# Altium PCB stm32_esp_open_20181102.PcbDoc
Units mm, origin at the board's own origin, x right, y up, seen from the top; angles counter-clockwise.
Board outline 48.1 x 88.05 mm, 2 copper layers (Top Layer, Bottom Layer); 96 components, 69 nets, 304 pads, 149 vias.
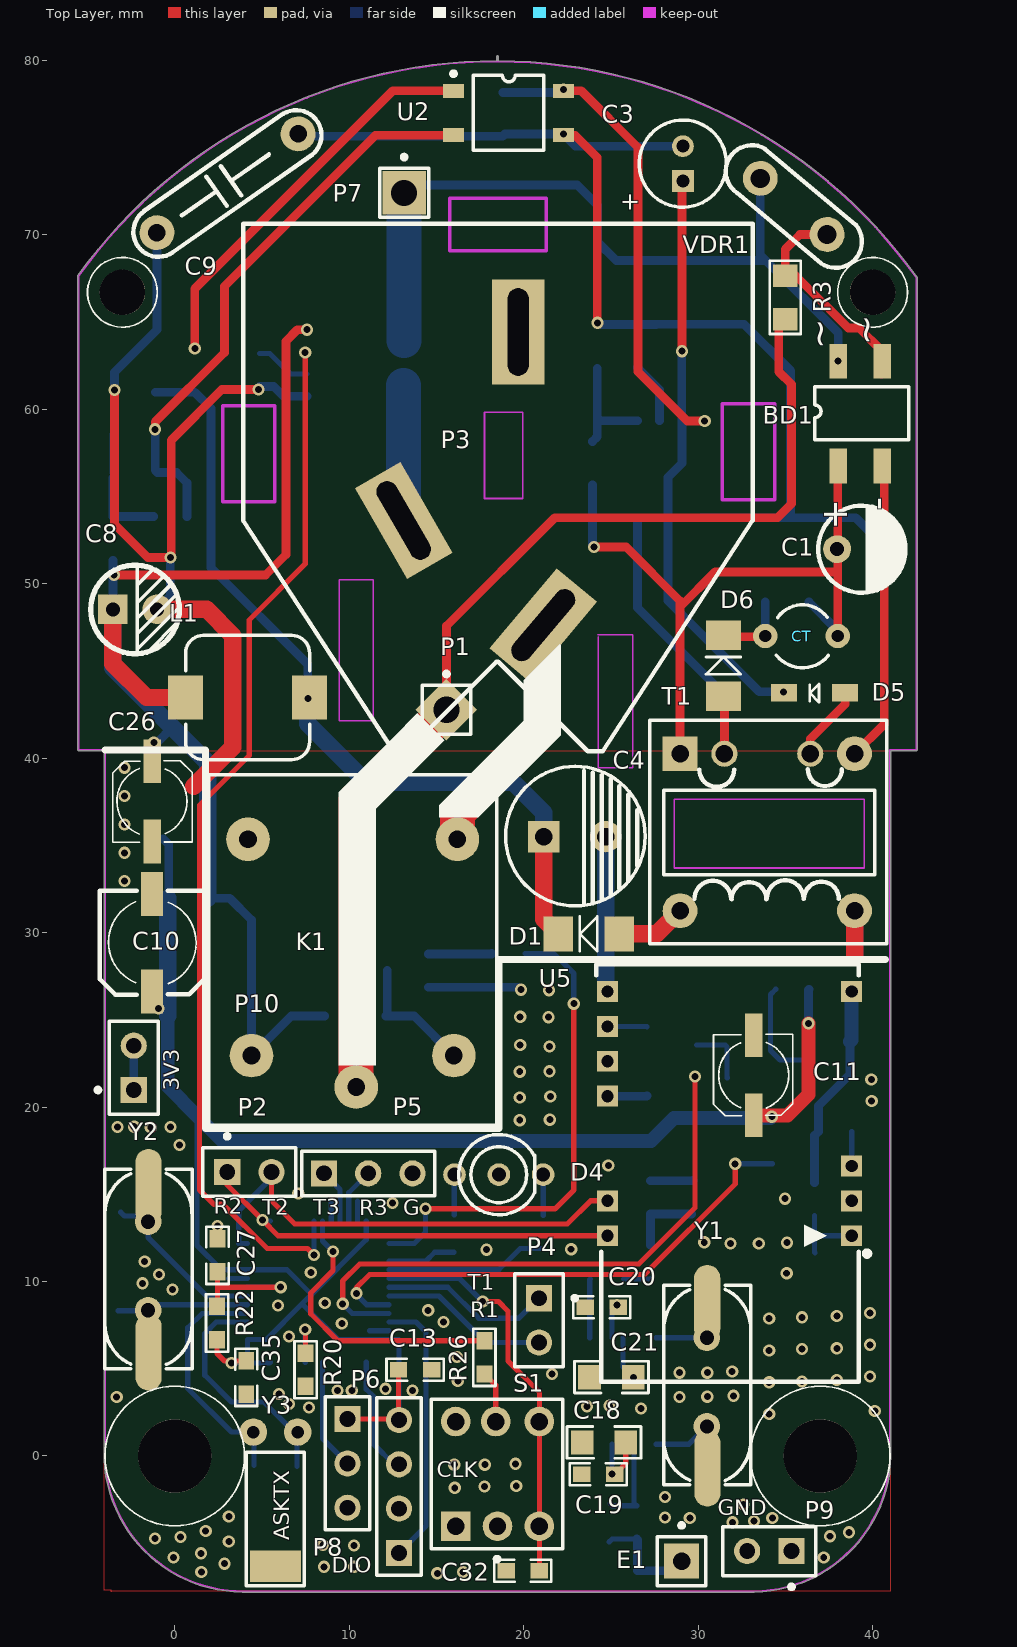
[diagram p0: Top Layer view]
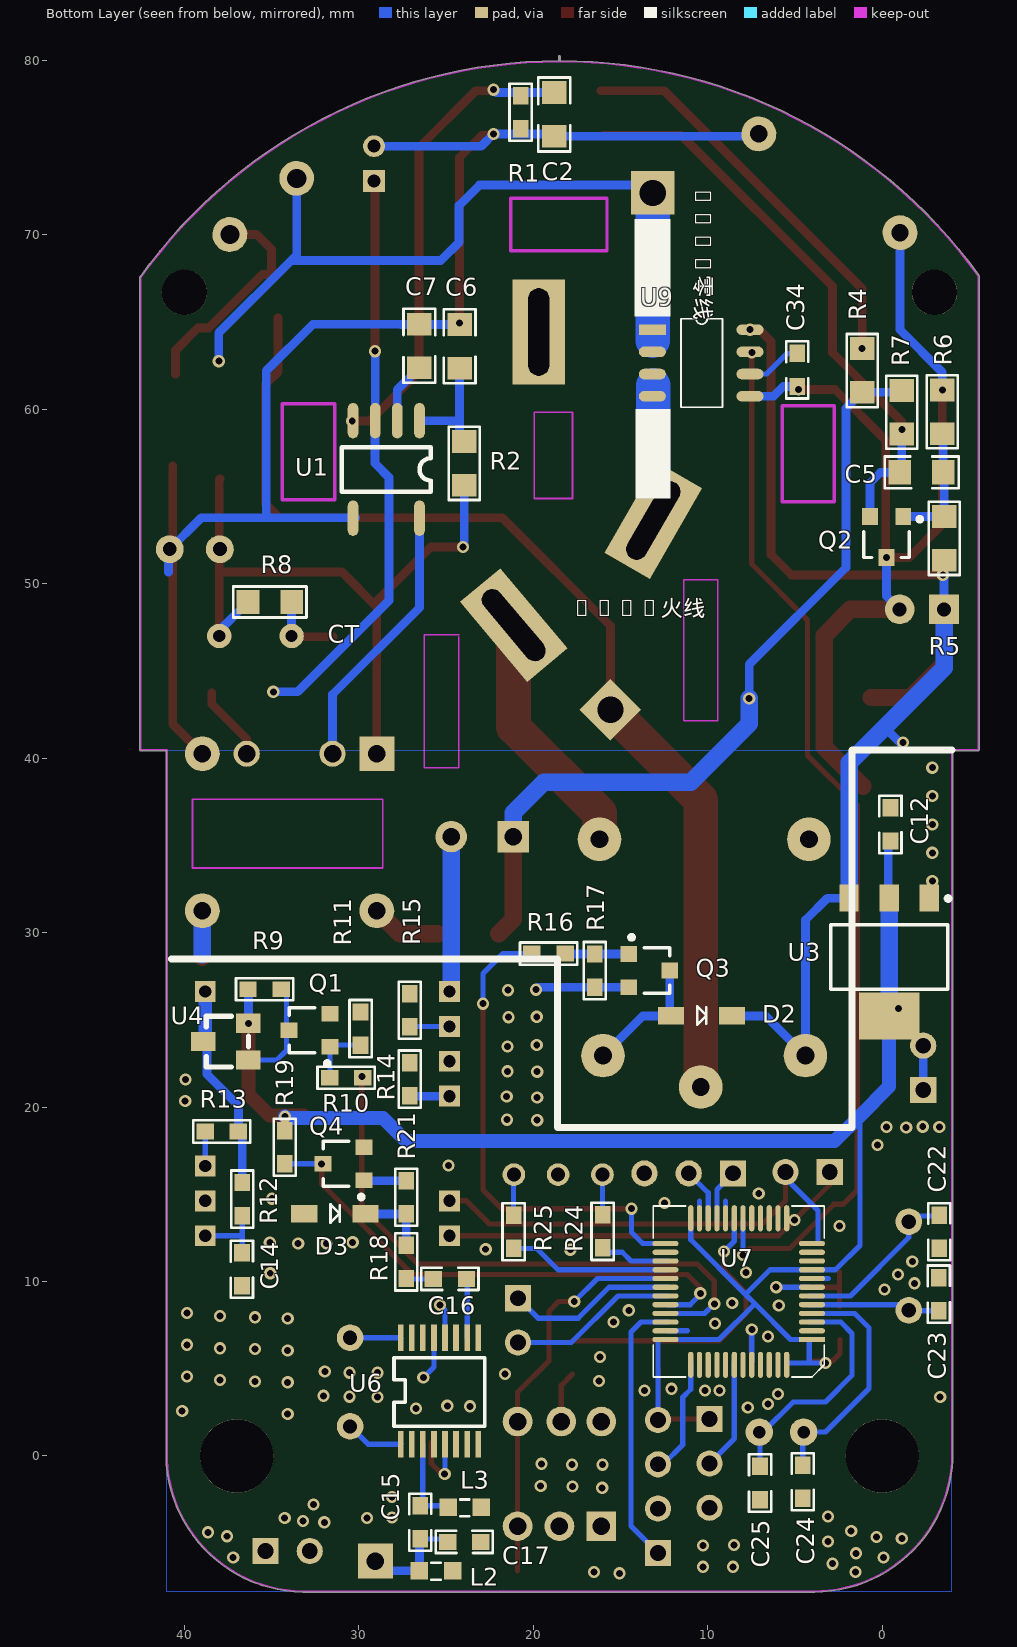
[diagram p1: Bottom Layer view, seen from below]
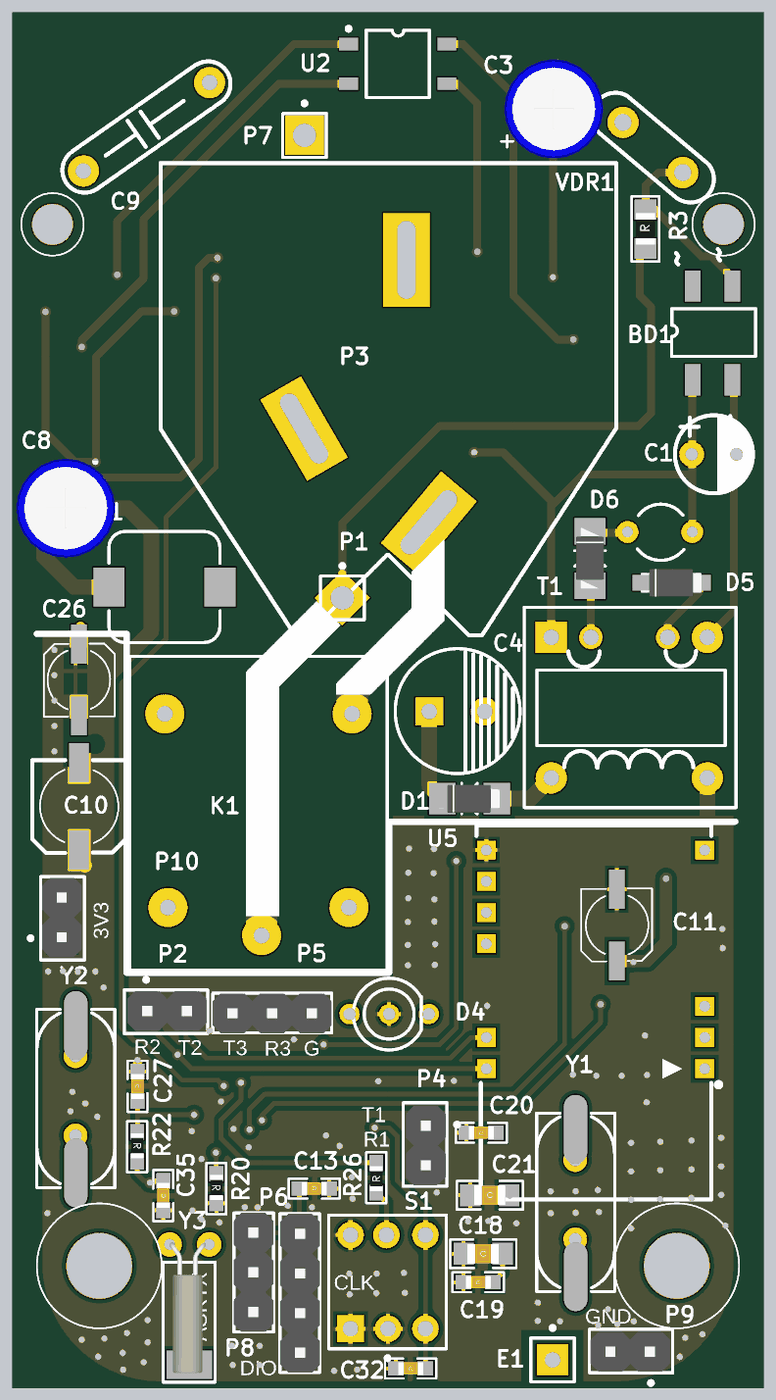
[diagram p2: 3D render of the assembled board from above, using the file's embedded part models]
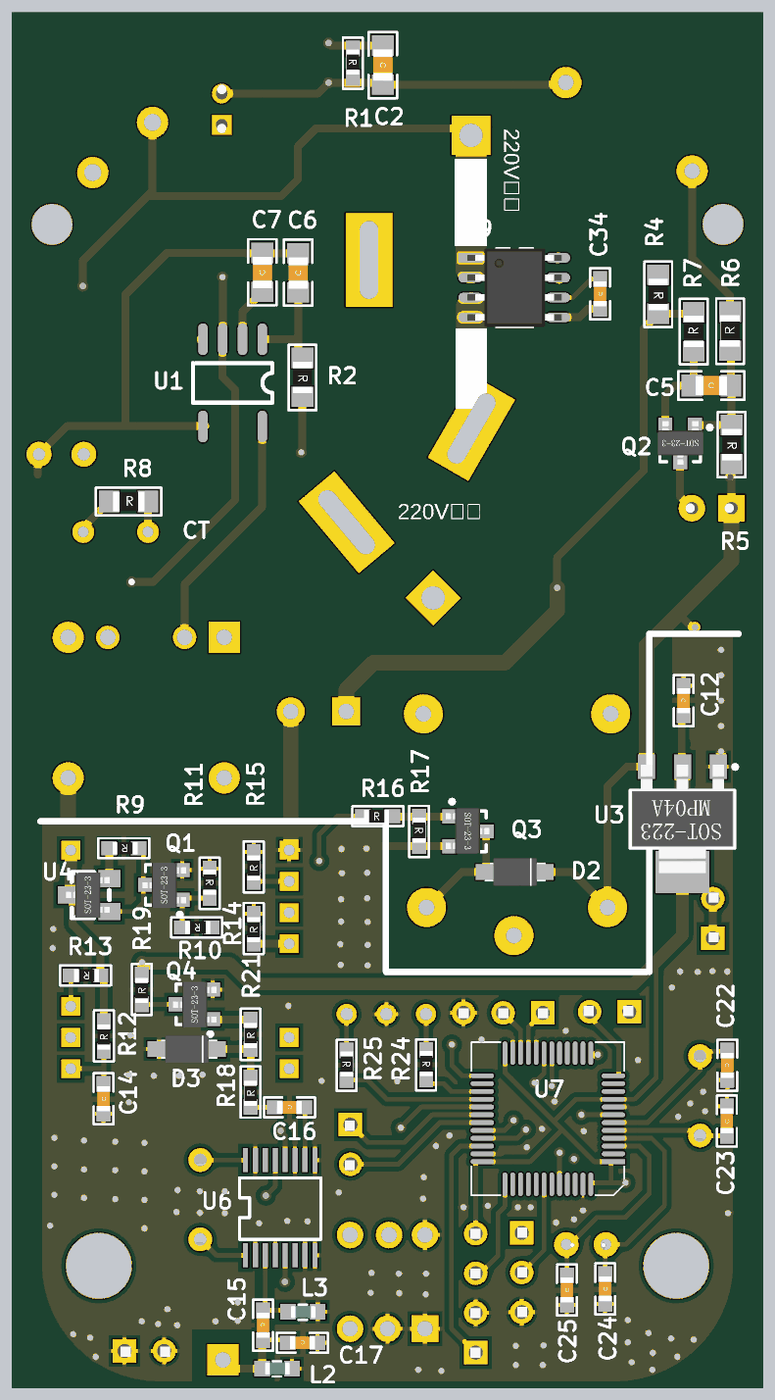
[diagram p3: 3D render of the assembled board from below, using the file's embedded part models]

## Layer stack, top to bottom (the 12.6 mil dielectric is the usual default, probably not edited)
Top Solder: solder mask 0.0102, Solder Resist, Dk 3.5
Top Layer: signal copper 0.0356
Dielectric 1: dielectric 0.32, FR-4, Dk 4.8
Bottom Layer: signal copper 0.0356
Bottom Solder: solder mask 0.0102, Solder Resist, Dk 3.5

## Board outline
-4.044,-0.198 cw(c-4,-0.172) -4.05,-0.172 -4.05,0.031 cw(c3.898,0.152) -4.051,0.049 cw(c-4,0.05) -4.05,0.055 -4.05,40.425 -5.5,40.425 cw(c-5.5,40.475) -5.55,40.475 -5.55,67.65 cw(c-5.5,67.65) -5.541,67.679 cw(c18.461,50.394) 18.45,79.972 18.45,80.2 cw(c18.5,80.2) 18.55,80.2 18.55,79.972 cw(c18.461,50.394) 42.529,67.588 cw(c42.5,67.546) 42.55,67.546 42.55,40.475 cw(c42.5,40.475) 42.5,40.425 41.05,40.425 41.05,0.025 cw(c41,0.025) 41.047,0.006 cw(c33.098,0.148) 33.201,-7.801 cw(c33.2,-7.75) 33.2,-7.801 3.898,-7.801 cw(c3.898,-7.75) 3.882,-7.798 cw(c3.898,0.152)

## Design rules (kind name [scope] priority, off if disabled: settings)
Clearance [All] p1: gap=0.3
PolygonConnect PolygonConnect_1 [isvia] p1: connectstyle=Direct reliefconductorwidth=0.254 reliefentries=4 polygonreliefangle="90 Angle" airgapwidth=0.254
PolygonConnect [All] p2: connectstyle=Relief reliefconductorwidth=0.254 reliefentries=4 polygonreliefangle="90 Angle" airgapwidth=0.254
RoutingVias [All] p1: holewidth=0.711 width=1.27 viastyle="Through Hole" minholewidth=0.711 minwidth=1.27 maxholewidth=0.711 maxwidth=1.27
SolderMaskExpansion [All] p1: expansion=0.102
Width [All] p1: maxlimit=10 minlimit=0.1 preferedwidth=0.254
30 further rules are at their usual default settings.

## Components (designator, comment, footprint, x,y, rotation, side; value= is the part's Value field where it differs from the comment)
BD1 "MB6S" MB6S 40.565,62.75 r270 top
C1 "4.7UF/400V" C-RB3_5X8mm 39.4,51.975 r0 top
C2 "0.01UF" CAP-0805 18.8,76.9 r270 bottom
C3 "22UF/50V" C-RB2_5x6.8mm 29.125,73.075 r90 top
C4 "1000UF/10V" C-RB3.5_8x12mm 22.925,35.503 r0 top
C5 "0.1UF" CAP-0805 -2.25,56.375 r180 bottom
C6 "0.01UF" CAP-0805 24.225,63.6 r90 bottom
C7 "331" CAP-0805 26.525,63.625 r90 bottom
C8 "220UF/10V" C-RB2.54_5x10mm -2.275,48.525 r0 top
C9 "Y-471M" C-RAD-Y_10mm 3.025,72.95 r215 top
C10 "220UF/6.3V" C-RB_S5mm -1.3,29.419 r90 top
C11 "220UF/6.3V" C-RB_S4mm 33.175,21.825 r90 top
C12 "0.1UF" CAP-0603 -0.475,36.2 r270 bottom
C13 "0.1UF" CAP-0603 13.775,4.95 r180 top
C14 "0.1UF" CAP-0603 36.7,10.7 r90 bottom
C15 "1.5PF" CAP-0603 26.475,-3.8 r270 bottom
C16 "0.1UF" CAP-0603 24.775,10.15 r0 bottom
C17 "5.6PF" CAP-0603 23.95,-4.925 r0 bottom
C18 "10UF" CAP-0805 24.6,0.775 r0 top
C19 "0.1UF" CAP-0603 24.275,-1.05 r0 top
C20 "0.1UF" CAP-0603 24.475,8.525 r0 top
C21 "10UF" CAP-0805 25.025,4.525 r0 top
C22 "20PF" CAP-0603 -3.275,12.85 r270 bottom
C23 "20PF" CAP-0603 -3.25,9.275 r90 bottom
C24 "20PF" CAP-0603 4.55,-1.475 r90 bottom
C25 "20PF" CAP-0603 7,-1.55 r90 bottom
C26 "220UF/6.3V" C-RB_S4mm -1.3,37.525 r270 top
C27 "0.1UF" CAP-0603 2.45,11.5 r270 top
C32 "0.1UF" CAP-0603 19.95,-6.575 r0 top
C34 "0.1UF" CAP-0603 4.875,62.25 r90 bottom
C35 "0.1UF" CAP-0603 4.1,4.5 r90 top
CT "222" C-RAD_4mm 35.925,47 r180 top
D1 "SR210" DIODE-1206 23.725,29.925 r180 top
D2 "1N4148" DIODE-1206_N 10.35,25.225 r180 bottom
D3 "1N4148" DIODE-1206_N 31.375,13.875 r180 bottom
D4 "LED2-DIP_1" LED-A3 18.575,16.125 r180 top
D5 "1N4148" DIODE-1206_N 36.675,43.75 r180 top
D6 "RS1M" DIODE-1206 31.45,45.3 r90 top
E1 "ANT_DIP" HDR1-ANT 29.05,-6.025 r0 top
K1 "10A继电器" SPDT-5 10.4,21.15 r90 top locked
L1 "10UH" IND-CD7_7X7mm 4.175,43.475 r180 top
L2 "24NH" IND-0603 24.625,-6.575 r0 bottom
L3 "39NH" IND-0603 22.975,-2.95 r0 bottom
P1 "220V_L" HDR1#1 15.575,42.775 r0 top
P2 "升级ESP" HDR2.54_2x1 4.275,16.275 r0 top
P3 "5孔插座" HDRFIVEHOLESOCHET 33.122,70.622 r180 top locked
P4 "COM_DEBUG" HDR2.54_2x1 20.875,7.775 r270 top
P5 "URAT3" HDR2.54_3X1 8.55,16.2 r0 top
P6 "SWD" HDR2.54_4X1 12.85,-5.555 r90 top
P7 "220V_N" HDR1#2 13.15,72.4 r0 top
P8 "RF" HDR2.54_3X1 9.9,2.115 r270 top
P9 "GND" HDR2.54_2x1 34.08,-5.45 r180 top
P10 "3V3" HDR2.54_2x1 -2.35,22.25 r90 top
Q1 "2N8050" SOT-23 32.825,24.4 r90 bottom
Q2 "T431" SOT-23 -0.25,52.675 r0 bottom
Q3 "2N8050" SOT-23 13.35,27.825 r270 bottom
Q4 "2N3904" SOT-23 30.875,16.75 r90 bottom
R1 "10K" RES-0603 20.725,77.975 r270 bottom
R2 "2.2M" RES-0805 23.95,58.15 r270 bottom
R3 "0R" RES-0805 35,65.15 r90 top
R4 "150R" RES-0805 1.15,63.475 r270 bottom
R5 "2.49K" RES-0805 -3.55,53.85 r270 bottom
R6 "2.4K" RES-0805 -3.45,58.6 r90 bottom
R7 "1K" RES-0805 -1.125,58.575 r90 bottom
R8 "100K" RES-0805 36.35,48.95 r180 bottom
R9 "100K" RES-0603 34.45,26.75 r0 bottom
R10 "10K" RES-0603 29.775,21.675 r0 bottom
R11 "47K" RES-0603 29.9,25.45 r270 bottom
R12 "10K" RES-0603 36.675,13.775 r90 bottom
R13 "100R" RES-0603 36.9,18.6 r0 bottom
R14 "0R" RES-0603 27.075,20.65 r90 bottom
R15 "1K" RES-0603 27.075,24.6 r90 bottom
R16 "4.7K" RES-0603 20.075,28.8 r180 bottom
R17 "47K" RES-0603 16.475,28.775 r270 bottom
R18 "1K" RES-0603 27.275,10.175 r90 bottom
R19 "1K" RES-0603 34.25,16.75 r90 bottom
R20 "100K" RES-0603 7.5,5.9 r270 top
R21 "10K" RES-0603 27.275,13.875 r90 bottom
R22 "100K" RES-0603 2.425,8.575 r270 top
R24 "1K" RES-0603 16.025,13.825 r270 bottom
R25 "510R" RES-0603 21.125,13.8 r270 bottom
R26 "1K" RES-0603 17.75,4.7 r90 top
S1 "带灯按钮" SW-PB6_B1 18.5,-1.025 r90 top locked
T1 "E10" EE10-6_10X9MM 28.965,40.25 r270 top
U1 "THX208" SOP-6 28.425,56.55 r270 bottom
U2 "356" SOP-4 19.125,76.98 r270 top
U3 "AMS1117" SOT-223 -0.4,28.6 r0 bottom
U4 "SI2301" SI2301 36.325,22.7 r180 bottom
U5 "ESP-12DIP" ESP_12DIP 38.8,12.625 r180 top locked
U6 "SYN500R" SO-16 27.6,0.679 r90 bottom
U7 "STM32F103C8T6" LQFP48 4.025,6.675 r0 bottom
U9 "ACS712" SOP-8 10.375,62.65 r180 bottom
VDR1 "7D471K" RES-DIP_5mm 35.475,71.625 r320 top
Y1 "13.560M" X-SM49T 30.525,4.3 r270 top
Y2 "8M" X-SM49T -1.5,10.95 r270 top
Y3 "32.768K" X-TC15-2DIP 7.045,1.371 r180 top

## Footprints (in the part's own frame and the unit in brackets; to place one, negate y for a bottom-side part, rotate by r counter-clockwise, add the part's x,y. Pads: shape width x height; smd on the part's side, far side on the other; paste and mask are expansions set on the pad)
C-RAD-Y_10mm [mm] "插件 2脚 10mm间距 开关电源高压Y电容"
  round 2 hole 1: 1(-4.938,0) 2(4.938,0)
  silkscreen extent -6.25,-1.44 6.27,1.45
C-RAD_4mm [mm] "插件 2脚 4mm间距"
  round 1.4 hole 0.7: 1(-2.074,0) 2(2.074,0)
  silkscreen extent -1.54,-1.78 1.44,1.82
C-RB2.54_5x10mm [mm] "插件 2脚 2.54mm间距"
  rect 1.7x1.7 hole 0.8: 1(-1.27,0)
  round 1.7 hole 0.8: 2(1.27,0)
  silkscreen extent -2.54,-2.54 2.54,2.54, body extent -3.05,-3.17 3.3,3.18, height 11.53
C-RB2_5x6.8mm [mm] "插件 2脚 2mm间距"
  rect 1.25x1.25 hole 0.75: 1(0,0)
  round 1.25 hole 0.75: 2(2,0)
  silkscreen extent -1.5,-2.5 3.5,2.5, body extent -2.16,-3.18 4.19,3.18, height 11.53
C-RB3.5_8x12mm [mm] "插件 2脚 3.5mm间距 直径8mm 高12mm"
  rect 1.8x1.8 hole 1: 1(-1.778,0)
  round 1.8 hole 1: 2(1.778,0)
  silkscreen extent -3.96,-3.97 4.04,4.03
C-RB3_5X8mm [mm] "插件 2脚 3mm间距"
  round 1.6 hole 0.8: 1(-1.435,0) 2(1.435,0)
  silkscreen extent -2.51,-2.5 2.49,2.5
C-RB_S4mm [mm] "贴片 直径4mm高 5.4mm"
  rect 2.5x1 smd: 1(-2.3,0) 2(2.3,0)
  silkscreen extent -2.32,-2.25 2.35,2.3
C-RB_S5mm [mm] "贴片 直径5mm 高5.4mm"
  rect 2.5x1.27 smd: 1(-2.794,0) 2(2.794,0)
  silkscreen extent -2.97,-3 2.97,3
CAP-0603 [mm] "贴片 长宽1.6x0.8mm"
  rect 1x0.9 smd: 1(-0.95,0) 2(0.95,0)
  silkscreen extent -1.64,-0.64 1.64,0.64, body extent -0.79,-0.41 0.81,0.4, height 0.88
CAP-0805 [mm] "贴片 长宽2.0x1.2mm"
  rect 1.3x1.4 smd: 1(-1.25,0) 2(1.25,0)
  silkscreen extent -2.11,-0.91 2.13,0.91, body extent -1.01,-0.62 1,0.63, height 0.92
DIODE-1206 [mm] "贴片   玻璃封装二极管 稳压 二极管宽焊盘"
  rect 1.7x2 smd: 1(-1.75,0) 2(1.75,0)
  silkscreen extent -0.5,-1 0.5,1, body extent -1.92,-0.89 1.98,0.89, height 1
DIODE-1206_N [mm] "贴片  玻璃封装二极管 窄焊盘"
  rect 1.5x1 smd: 1(-1.75,0) 2(1.75,0)
  silkscreen extent -0.25,-0.5 0.27,0.55, body extent -1.92,-0.89 1.98,0.89, height 1
EE10-6_10X9MM [mm] "插件 6脚  变压器"
  round 2 hole 1: 1(0,10) 5(9,10) 6(9,0)
  round 1.5 hole 1: 2(0,7.46) 3(0,2.54)
  rect 2x2 hole 1: 4(0,0)
  silkscreen extent -1.93,-1.73 10.9,11.84
ESP_12DIP [mm] "ESP-12 Wi-Fi Module by AI-Thinker"
  rect 1.2x1.2 hole 0.7: 1(0,0) 2(0,-2) 3(0,-4) 8(0,-14) 9(14,-14) 10(14,-12) 11(14,-10) 12(14,-8) 15(14,-2) 16(14,0)
  silkscreen extent -1.03,-15.57 14.63,8.37
HDR1#1 [mm] "插件 1脚"
  rect 2.5x2.5 hole 1.5 rot 45: 1(0,0)
  silkscreen extent -1.4,-1.4 1.4,2.17
HDR1#2 [mm] "插件 1脚"
  rect 2.5x2.5 hole 1.5: 1(0,0)
  silkscreen extent -1.4,-1.4 1.4,2.17
HDR1-ANT [mm] "插件 1脚"
  rect 2x2 hole 1: 1(0,0)
  silkscreen extent -1.4,-1.4 1.4,2.17
HDR2.54_2x1 [mm] "插件 2脚"
  rect 1.5x1.5 hole 0.9: 1(-1.27,0)
  round 1.5 hole 0.9: 2(1.27,0)
  silkscreen extent -2.67,-1.4 2.67,2.17, body extent -2.47,-1.22 2.61,1.32, height 8.54
HDR2.54_3X1 [mm] "插件 3脚"
  rect 1.5x1.5 hole 0.9: 1(0,0)
  round 1.5 hole 0.9: 2(2.54,0) 3(5.08,0)
  silkscreen extent -1.27,-1.27 6.35,1.27, body extent -1.29,-1.3 6.33,1.24, height 8.54
HDR2.54_4X1 [mm] "插件 4脚"
  rect 1.5x1.5 hole 0.9: 1(0,0)
  round 1.5 hole 0.9: 2(2.54,0) 3(5.08,0) 4(7.62,0)
  silkscreen extent -1.27,-1.27 8.89,1.27, body extent -1.28,-1.29 8.88,1.25, height 8.54
HDRFIVEHOLESOCHET [mm] "五孔插座"
  rect 3x6 hole 5 slot 1.2 at 0 deg: 1(13.437,6.198)
  rect 3x6 hole 5 slot 1.2 at 140 deg rot 140: 2(12,23)
  rect 3x6 hole 5 slot 1.2 at 30 deg rot 30: 3(20,17)
  Keep-Out Layer lines w0.2: 30.381,15.922 27.381,15.922 27.381,10.414 30.381,10.414 30.381,15.922 ; 17.348,1.527 17.348,-1.473 11.84,-1.473 11.84,1.527 17.348,1.527 ; 1.73,15.82 1.73,10.312 -1.27,10.312 -1.27,15.82 1.73,15.82
  silkscreen extent 0,0 29.2,30.23
IND-0603 [mm] "贴片 电感1.6x0.8mm  1608"
  rect 1x1 smd: 1(0,0) 2(1.9,0)
  silkscreen extent 0.69,-0.46 1.22,0.51, body extent 0.12,-0.4 1.72,0.4, height 0.95
IND-CD7_7X7mm [mm] "贴片 电感7*7"
  rect 2x2.5 smd: 1(-3.556,0) 2(3.556,0)
  silkscreen extent -3.56,-3.56 3.56,3.56, body extent -3.56,-3.56 3.56,3.56, height 4
LED-A3 [mm] "插件 3脚 双色LED"
  round 1.3 hole 0.8: 1(-2.54,0) 2(0,0) 3(2.54,0)
  silkscreen extent -2.06,-2.3 2.3,2.3
LQFP48 [mm] "贴片 48引脚"
  rect 1.5x0.3 smd: 1(0,0)
  oval 1.5x0.3 smd: 2(0,-0.5) 3(0,-1) 4(0,-1.5) 5(0,-2) 6(0,-2.5) 7(0,-3) 8(0,-3.5) 9(0,-4) 10(0,-4.5) 11(0,-5) 12(0,-5.5) 25(8.4,-5.5) 26(8.4,-5) 27(8.4,-4.5) 28(8.4,-4) 29(8.4,-3.5) 30(8.4,-3) 31(8.4,-2.5) 32(8.4,-2) 33(8.4,-1.5) 34(8.4,-1) 35(8.4,-0.5) 36(8.4,0)
  oval 0.3x1.5 smd: 13(1.45,-6.95) 14(1.95,-6.95) 15(2.45,-6.95) 16(2.95,-6.95) 17(3.45,-6.95) 18(3.95,-6.95) 19(4.45,-6.95) 20(4.95,-6.95) 21(5.45,-6.95) 22(5.95,-6.95) 23(6.45,-6.95) 24(6.95,-6.95) 37(6.95,1.45) 38(6.45,1.45) 39(5.95,1.45) 40(5.45,1.45) 41(4.95,1.45) 42(4.45,1.45) 43(3.95,1.45) 44(3.45,1.45) 45(2.95,1.45) 46(2.45,1.45) 47(1.95,1.45) 48(1.45,1.45)
  silkscreen extent -0.7,-7.65 9.1,2.15
MB6S [mm] "贴片 4脚 整流桥"
  rect 2x1 smd: 1(0,0) 2(0,-2.54) 3(6,-2.54) 4(6,0)
  silkscreen extent 1.45,-3.89 4.5,1.5
RES-0603 [mm] "贴片 2脚 1.6x0.8mm"
  rect 1x0.9 smd: 1(0,0) 2(1.9,0)
  silkscreen extent -0.69,-0.64 2.59,0.64, body extent 0.08,-0.4 1.68,0.41, height 0.53
RES-0805 [mm] "贴片 2脚 2.0x1.3mm"
  rect 1.3x1.4 smd: 1(0,0) 2(2.5,0)
  silkscreen extent -0.84,-0.89 3.35,0.89, body extent 0.26,-0.62 2.27,0.62, height 0.53
RES-DIP_5mm [mm] "插件 2脚 电阻 间距5mm"
  round 2 hole 1.1: 1(-2.5,0) 2(2.5,0)
  silkscreen extent -4.62,-1.5 4.65,1.47
SI2301 [mm] "贴片 3脚 PMOS开关管"
  rect 1.4x1.1 smd: 1(0,0) 2(0,2.1) 3(-2.6,1.05)
  silkscreen extent -2.41,-0.4 0,2.5, body extent -2.77,-0.4 0.03,2.5, height 1.2
SO-16 [mil] "贴片 16脚"
  rect 60x13 smd: 1(0,0) 2(0,-25) 3(0,-50) 4(0,-75) 5(0,-100) 6(0,-125) 7(0,-150) 8(0,-175) 9(240,-175) 10(240,-150) 11(240,-125) 12(240,-100) 13(240,-75) 14(240,-50) 15(240,-25) 16(240,0)
  silkscreen extent 40,-190 195,15
SOP-4 [mm] "贴片 4脚 一般应该在光耦"
  rect 0.8x1.2 smd: 1(-1.27,-3.15) 2(1.27,-3.15) 3(1.27,3.15) 4(-1.27,3.15)
  silkscreen extent -2.37,-3.27 2.15,2.02
SOP-6 [mil] "贴片 6脚 开关电源IC"
  oval 80x24 smd: 1(-110,75) 2(-110,25) 3(-110,-25) 4(-110,-75) 5(110,-75) 8(110,75)
  silkscreen extent -50,-100 50,100
SOP-8 [mil] "贴片 8脚"
  rect 61x24 smd: 1(-110.24,75)
  oval 61x24 smd: 2(-110.24,25) 3(-110.24,-25) 4(-110.24,-75) 5(110.24,-75) 6(110.24,-25) 7(110.24,25) 8(110.24,75)
  silkscreen extent -46,-100 48,100, body extent -118,-99 120,99, height 63
SOT-23 [mm] "贴片 3脚"
  rect 0.9x0.95 smd: 1(-0.95,-1.175) 2(0.95,-1.175) 3(0,1.175)
  silkscreen extent -2.03,-1.14 1.3,1.18, body extent -1.48,-1.42 1.42,1.38, height 1.2
SOT-223 [mm] "贴片 3脚"
  rect 1.1x1.55 smd: 1(-2.3,-3.375) 2(0,-3.375) 3(2.3,-3.375)
  rect 3.45x2.7 smd: 2(0,3.375)
  silkscreen extent -3.5,-3.48 3.35,1.85, body extent -3.25,-3.5 3.25,3.46, height 1.7
SPDT-5 [mm] "插件 5脚 单刀单掷继电器DIP"
  round 2.5 hole 1.016: 1(1.8,6) 2(1.8,-5.6) 3(0,0) 4(14.2,6.2) 5(14.2,-5.8)
  silkscreen extent -2.2,-8.05 17.89,8.45
SW-PB6_B1 [mm] "带灯按键"
  rect 1.7x1.7 hole 1: 1(-3,2.4)
  round 1.7 hole 1: 2(-3,0) 3(-3,-2.4) 4(3,-2.4) 5(3,0.1) 6(3,2.4)
  silkscreen extent -5.01,-3.75 4.28,3.8
X-SM49T [mm] "贴片插件 2脚 晶振"
  round 1.524 hole 0.813: 1(2.6,-0.025) 2(-2.48,-0.025)
  oval 4.4x1.5 smd: 1(5,0.004) 2(-4.45,-0.004)
  silkscreen extent -5.47,-2.5 5.94,2.5
X-TC15-2DIP [mil] "插件 2脚 圆柱晶振"
  round 62 hole 28: 1(0,0) 2(100,0)
  rect 114.17x70.87 smd: ""(50,303)
  silkscreen extent -15,45 116,347, body extent 9,-4 100,324, height 77

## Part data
BD1: "整流桥"
C1 C3 C4 C8: library part CAP2, "极性电容DIP"
C2 C5 C6 C7 C12 C13 C14 C15 C16 C17 C18 C19 C20 C21 C22 C23 C24 C25 C27 C32 C34 C35: library part CAP, "无极电容SMD"
C9 CT: library part CAP2-POL, "无极电容DIP"
C10 C11 C26: library part CAP-POL, "极性电容SMD"
D1 D2 D3 D5 D6: library part DIODE-SMD, "二极管SMD"
D4: "共阴双色LED"
E1: "RF天线插件"
K1: library part Relay-SPDT-2, "单杆单掷继电器普通用"
L1 L2 L3: library part Inductor-SMD, "电感SMD"
P1 P7: library part "Header 1X1", "单排针"
P2 P4 P9 P10: library part "Header 2X1", "单排针"
P3 P5 P8: library part "Header 3X1", "单排针"
P6: library part "Header 4X1", "单排针"
Q1 Q3 Q4: "NPN三极管"
Q2: "T431基准稳压"
R1 R2 R3 R4 R5 R6 R7 R8 R9 R10 R11 R12 R13 R14 R15 R16 R17 R18 R19 R20 R21 R22 R24 R25 R26: library part RES, "电阻SMD"
S1: library part SW-PB6_DIP_1, "带灯按键开关"
T1: library part "Trans Cupl", "变压器（耦合电感)"
U1: "THX208开关电源芯片"
U2: library part Optoisolator1, "4引脚光电耦合器"
U3: "LDO降压芯片"
U4: "PMOS开关管"
U6: library part MICRF211, "MICRF211"
U7: "Medium-density performance line ARM-based 32-bit MCU with 64KB Flash, USB, CAN, 7 timers, 2 ADCs"
U9: "ACS712电流检测IC"
VDR1: library part "Res Varistor_DIP", "压敏电阻DIP 07D系列压敏"
Y1 Y2: library part XTAL-2_SMD, "无源晶振SMD"
Y3: library part XTAL-2_DIP_1, "圆晶振DIP"

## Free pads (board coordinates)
  round 4.2 hole 4.2: 0(0,0) 0(37,0)
  round 2.6 hole 2.6: 1(-3,66.7) 1(40,66.7)

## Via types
v1: diameter 0.7, hole 0.4, Top Layer to Bottom Layer, tented both sides, 147 vias
v2: diameter 0.7, hole 0.4, Top Layer to Bottom Layer, 2 vias

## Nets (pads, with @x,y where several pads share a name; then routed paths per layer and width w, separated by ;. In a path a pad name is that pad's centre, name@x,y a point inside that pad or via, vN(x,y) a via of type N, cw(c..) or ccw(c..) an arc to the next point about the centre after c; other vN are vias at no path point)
2LED_G: R24.2 U7.27 | length 3.9
  Bottom Layer w0.3: U7.27@12.275,11.175 14.4,11.175 14.9,11.675 R24.2@16,11.675
2LED_R: R25.2 U7.28 | length 9.4
  Bottom Layer w0.3: U7.28@12.275,10.675 18.575,10.675 19.8,11.9 R25.2
3V3: C10.1 C11.1 C12.2 C13.2 C35.2 P6.4 P8.1 P10.1 P10.2 R9.2 R19.2 R22.2 U3.2 U4.2 U7.1 U7.9 U7.24 U7.36 U7.48 | length 112.7
  Top Layer w0.3: R22.2 2.425,5.875 2.85,5.45 C35.2 ; P8.1 12.8,2.115 12.825,2.14 C13.2
  Top Layer w0.5: C11.1 33.25,19.45 v1(34.225,19.45)
  Top Layer w0.8: C11.1 35.125,19.525 36.325,20.725 v1(36.325,24.8)
  Bottom Layer w0.3: 1.275,19.5 1.275,12.075 2.675,10.675 6.425,10.675 7.8,9.3 7.8,9.225 7.3,8.725 ; v1(3.25,5.325) 4.225,5.325 ; U7.48@5.475,5.375 5.425,5.325 4.225,5.325 ; 7.838,9.262 10.975,12.4 U7.24@10.975,13.475 ; P6.4 12.85,6.675 9.35,6.675 7.3,8.725 ; 4.225,5.325 4.175,5.375 4.175,6.675 5.25,6.675 7.3,8.725
  Bottom Layer w0.5: P10.1 P10.2 ; C12.2@-0.675,35.375 -0.35,35.05 U3.2@-0.35,31.775 ; v1(36.325,24.8) 36.325,26.725 R9.2
  Bottom Layer w0.8: U3.2@-0.4,25.225 -0.4,21.175 1.275,19.5 2.725,18.05 27.3,18.05 28.625,19.375 34.15,19.375 v1(34.225,19.45)
  Bottom Layer w1: U3.2@-0.4,25.225 U3.2@-0.4,31.975
  other v2: -0.925,25.65
5V: C8.1 C26.1 D2.2 K1.1 L1.2 R5.2 U3.3 U9.8 | length 71.1
  Top Layer w0.5: v1(-3.475,50.5) 5.2,50.5 6.375,51.675 6.375,63.9 7.03,64.555 v1(7.575,64.555)
  Top Layer w1: C8.1 -3.545,45.42 -1.6,43.475 L1.2
  Bottom Layer w0.5: R5.2 -3.545,51.345 C8.1 ; v2(-1.2,40.9) -1,40.9 -0.138,41.762 ; U3.3 3.15,31.975 4.4,30.725 K1.1 6.675,25.225 D2.2
  Bottom Layer w1: C8.1 -3.545,45.17 -0.138,41.762 1.9,39.725 U3.3
220V_L: K1.3 P1.1 R3.1 | length 62.2
  Top Layer w0.5: P1.1 15.575,47.575 21.775,53.775 34.55,53.775 35.35,54.575 35.35,61.425 34.625,62.15 R3.1@34.625,65.225
  Top Layer w2: K1.3 10.4,37.6 P1.1
220V_N: BD1.2 P7.1 U9.1 U9.2 VDR1.1 | length 44.7
  Bottom Layer w0.5: P7.1 13.6,72.85 23.075,72.85 24.25,71.675 24.25,69.575 25.3,68.525 33.875,68.525 ; VDR1.1 33.56,68.84 33.875,68.525 ; v1(38.025,62.75) 38.025,64.375 33.875,68.525
  Bottom Layer w2: 13.15,63.925 P7.1
ACS712_ADC: U7.18 U9.7 | length 60.5
  Top Layer w0.3: v1(7.475,63.25) 7.475,51.125 4.275,47.925 4.275,40.15 1.425,37.3 1.425,15.25 2.25,14.425 2.775,14.425 5.3,11.9 7.6,11.9 v1(7.975,11.525)
  Bottom Layer w0.3: v1(7.975,11.525) U7.18@7.975,13.475
ASK_RX: Q4.3 R19.1 U7.32 | length 30
  Top Layer w0.3: v1(10.425,9.325) 10.425,9.65 11.175,10.4 26.925,10.4 32.125,15.6 v1(32.125,16.75)
  Bottom Layer w0.3: v1(10.425,9.325) 10.425,9.25 11,8.675 U7.32@12.275,8.675 ; Q4.3 R19.1
ASK_TX: P8.2 U7.42 | length 6.4
  Bottom Layer w0.3: U7.42@8.475,5.375 8.475,1 P8.2
DEBUG_RX: P4.1 U7.30 | length 9.8
  Bottom Layer w0.3: U7.30@12.275,9.675 15.65,9.675 17.425,7.9 19.73,7.9 P4.1
DEBUG_TX: P4.2 U7.31 | length 9.7
  Bottom Layer w0.3: U7.31@12.275,9.175 15.15,9.175 17.82,6.505 P4.2
ESP_ONOFF: R10.1 U7.33 | length 33.6
  Top Layer w0.3: v1(9.625,8.725) 9.625,10.025 10.6,11 26.6,11 29.825,14.225 v1(29.825,21.75)
  Bottom Layer w0.3: v1(9.625,8.725) 10.175,8.175 U7.33@12.275,8.175
ESP_RX: P2.2 U5.15 U7.12 | length 27.4
  Top Layer w0.3: P2.2 5.545,14.63 6.875,13.3 22.5,13.3 23.825,14.625 U5.15
  Bottom Layer w0.3: U7.12@4.175,12.175 3.675,12.175 3.675,14.075 5.595,15.995 P2.2@5.595,16.275
ESP_TX: P2.1 U5.16 U7.13 | length 24.2
  Top Layer w0.3: P2.1 3.005,15.545 v1(5.025,13.525) 5.925,12.625 U5.16
  Bottom Layer w0.3: v1(5.025,13.525) 5.075,13.475 U7.13@5.475,13.475
GND: C4.2 C8.2 C9.2 C10.2 C11.2 C12.1 C13.1 C14.1 C17.1 C18.1 C19.1 C20.1 C21.1 C22.2 C23.2 C24.1 C25.1 C26.2 C27.1 C32.1 C34.1 C35.1 D3.1 D4.2 L2.1 L3.1 P5.3 P6.2 P8.3 P9.1 P9.2 Q1.2 Q2.3 Q3.2 Q4.2 R6.2 R11.1 R14.2 R15.2 R17.2 R20.2 S1.1 S1.2 S1.6 T1.5 U3.1 U5.9 U6.2 U6.4 U6.7 U6.8 U6.9 U6.11 U6.15 U7.8 U7.20 U7.23 U7.35 U7.47 U9.5 | length 79.4
  Top Layer w0.5: v1(-3.45,61.1) -3.45,53.4 -1.55,51.5 v1(-0.25,51.5) -0.2,51.55 -0.2,58.225 2.7,61.125 v1(4.8,61.125)
  Top Layer w1: C8.2 1.825,48.525 3.325,47.025 3.325,40.625 1.1,38.4 ; 38.965,28.585 T1.5
  Bottom Layer w0.3: 3.075,10.175 U7.8@4.175,10.175 ; U7.20@8.975,13.475 8.975,14.6 ; U7.23@10.475,13.475 10.475,14.6 ; 11.175,7.175 U7.35@12.275,7.175
  Bottom Layer w0.5: v1(-3.45,61.1) -3.45,62.125 -1.02,64.555 C9.2 ; C8.2 -0.25,49.28 v1(-0.25,51.5) ; C34.1 5.675,61.3 6.23,60.745 U9.5 ; Q3.2 R17.2 19.7,26.875 v1(19.85,26.725)
  Bottom Layer w1: C4.2 24.703,26.625 U5.9 ; 38.965,28.735 T1.5
  other v1: 15.05,-6.725 1.525,-6.65 16.525,-6.65 8.55,-6.35 10.275,-6.35 2.85,-6.175 -0.075,-5.825 37.2,-5.825 1.5,-5.575 10.275,-5.125 8.5,-5.1 3.1,-4.9 -1.125,-4.725 0.325,-4.65 37.55,-4.6 38.65,-4.375 1.775,-4.3 31.975,-3.8 33.2,-3.725 29.525,-3.55 34.25,-3.55 28.1,-3.525 3.1,-3.475 32.6,-2.775 28.1,-2.35 16.05,-1.825 17.75,-1.75 19.575,-1.725 16.025,-0.5 17.775,-0.5 19.525,-0.45 34.075,2.4 40.125,2.575 26.725,2.725 7.7,2.775 23.625,2.85 24.925,2.875 6.55,2.975 -3.325,3.375 28.925,3.375 30.525,3.4 32.025,3.45 5.975,3.55 9.325,3.75 10.15,3.75 13.625,3.75 12.075,3.85 34.075,4.225 35.95,4.275 16.225,4.3 37.95,4.35 39.85,4.55 21.625,4.7 28.925,4.775 30.525,4.775 31.95,4.85 16.175,5.675 34.075,6.05 35.95,6.125 37.95,6.175 39.85,6.375 6.55,6.85 9.575,7.6 15.4,7.675 34.075,7.875 35.95,7.95 37.95,8.025 39.85,8.2 14.525,8.35 5.925,8.625 8.6,8.775 -0.125,9.55 -1.85,9.9 -0.9,10.4 35.075,10.475 7.8,10.525 -1.725,11.15 17.875,11.825 22.725,11.85 31.85,12.175 33.475,12.175 35.1,12.225 30.35,12.25 2.45,13.175 12.475,14.5 34.975,14.75 7.075,15.05 24.85,16.65 0.275,17.825 -1.375,18.825 -3.275,18.85 -0.25,18.85 -2.325,18.875 19.775,19.25 21.5,19.275 39.95,20.35 19.775,20.55 21.525,20.6 39.925,21.575 19.775,22.025 21.475,22.05 21.475,23.475 19.8,23.55 21.425,25.15 19.8,25.175 21.45,26.7 -2.875,32.95 -2.875,34.575 -2.875,36.2 -2.875,37.825 -2.875,39.45
KEY2: C32.2 S1.3 S1.4 U7.29 | length 23.2
  Top Layer w0.3: v1(17.65,8.85) 18.55,8.85 19.1,8.3 19.1,5.45 20.9,3.65 S1.4 S1.3 C32.2
  Bottom Layer w0.3: U7.29@12.275,10.175 16.325,10.175 v1(17.65,8.85)
KEY2LED: R26.2 U7.19 | length 16.7
  Top Layer w0.3: v1(9.075,11.725) 9.075,10.625 7.8,9.35 7.8,8.15 9.35,6.6 R26.2
  Bottom Layer w0.3: U7.19@8.475,13.475 8.475,12.325 v1(9.075,11.725)
NetBD1_1: BD1.1 R3.2 VDR1.2 | length 12.9
  Top Layer w0.5: VDR1.2 35.843,70.018 35,69.175 35,67.725 35.525,67.725 38.6,64.65 39.225,64.65 40.5,63.375 BD1.1@40.5,62
NetBD1_3: BD1.3 C1.1 CT.1 R2.2 R8.1 T1.4 | length 40.1
  Top Layer w0.5: v1(24.025,52.1) 25.875,52.1 28.965,49.01 28.965,48.665 ; T1.4 28.965,48.665 ; BD1.3@37.96,56 37.999,55.961 37.999,50.675 ; CT.1 37.999,50.675 ; 28.965,48.665 30.975,50.675 37.999,50.675
  Bottom Layer w0.5: R2.2 23.95,52.175 v1(24.025,52.1) ; R8.1 37.999,47.301 CT.1
NetC2_1: C2.1 R1.1 U1.4 U2.4 | length 27
  Top Layer w0.5: U2.4 23.3,78.25 26.55,75 26.55,62.15 29.375,59.325 v1(30.375,59.325)
  Bottom Layer w0.5: C2.1 22.11,78.15 v1(22.275,78.315)
NetC3_1: C3.1 D5.2 U1.3 | length 33.1
  Top Layer w0.5: v1(29.075,63.325) 29.075,73.025 C3.1
  Bottom Layer w0.5: U1.3 29.06,63.31 v1(29.075,63.325) ; U1.3@29.075,59.204 29.075,56.9 28.275,56.1 28.275,49.025 33.5,43.8 v1(34.9,43.8)
NetC4_1: C4.1 D1.2 L1.1 R4.2 R7.2 | length 46.9
  Top Layer w1: C4.1 21.147,30.753 D1.2
  Bottom Layer w0.5: R7.2@-1.1,60.975 R4.2 2.075,60.05 2.075,50.925 7.625,45.375 v1(7.625,43.425)
  Bottom Layer w1: v1(7.625,43.425) 7.625,41.975 10.975,38.625 19.4,38.625 21.147,36.878 C4.1
NetC5_1: C5.1 Q2.2 R7.1 U2.2 | length 33
  Top Layer w0.5: v1(-1.125,58.85) -1.125,59.275 2.85,63.25 2.85,67.05 11.51,75.71 U2.2
  Bottom Layer w0.5: v1(-1.125,58.85) R7.1 -1.125,56.5 C5.1 0.1,56.375 0.7,55.775 Q2.2
NetC5_2: C5.2 Q2.1 R5.1 R6.1 | length 6.8
  Bottom Layer w0.5: C5.2@-3.55,56.075 R5.1 Q2.1 ; C5.2 -3.5,58.55 R6.1
NetC6_1: C6.1 R2.1 U1.1 | length 6.7
  Bottom Layer w0.5: R2.1 24.225,58.425 24.225,59.525 ; C6.1 24.225,59.525 ; U1.1 24.406,59.344 24.225,59.525
NetC7_1: C7.1 U1.2 | length 3.6
  Bottom Layer w0.5: C7.1 27.79,61.11 U1.2
NetC14_2: C14.2 R12.1 U5.1 | length 4.3
  Bottom Layer w0.3: R12.1 36.675,12.65 ; C14.2 36.675,11.675 36.675,12.65 ; U5.1 36.7,12.625 36.675,12.65
NetC15_1: C15.1 L3.2 U6.3 | length 5.2
  Bottom Layer w0.3: L3.2@24.95,-2.725 25.075,-2.85 C15.1 26.33,-2.705 U6.3
NetC15_2: C15.2 C17.2 E1.1 L2.2 | length 6.2
  Bottom Layer w0.3: C17.2 25.075,-4.75 C15.2
  Bottom Layer w0.5: C15.2 26.525,-4.8 L2.2 28.5,-6.575 E1.1
NetC16_1: C16.1 U6.10 | length 3.4
  Bottom Layer w0.3: U6.10 23.79,10.115 C16.1
NetC16_2: C16.2 R18.1 | length 1.6
  Bottom Layer w0.3: C16.2 27.25,10.15 R18.1
NetC18_2: C18.2 C19.2 U6.5 | length 3.8
  Top Layer w0.3: C19.2 25.85,-0.425 C18.2
  Bottom Layer w0.3: U6.5 25.06,-1.01 v1(25.075,-1.025)
NetC20_2: C20.2 U6.12 | length 2
  Bottom Layer w0.3: U6.12 25.06,8.36 v1(25.35,8.65)
NetC21_2: C21.2 U6.13 | length 2.5
  Bottom Layer w0.3: U6.13 25.695,5.105 v1(26.3,4.5)
NetC22_1: C22.1 U7.6 Y2.2 | length 9.8
  Bottom Layer w0.3: C22.1@-3.1,13.975 -2.875,13.75 -1.845,13.75 -1.525,13.43 -1.525,12.525 1.825,9.175 U7.6@4.175,9.175
NetC23_1: C23.1 U7.5 Y2.1 | length 7.6
  Bottom Layer w0.3: C23.1 -1.55,8.325 -1.525,8.35 -1.2,8.675 U7.5@4.175,8.675
NetC24_2: C24.2 U7.4 Y3.2 | length 13.9
  Bottom Layer w0.3: U7.4@4.175,8.175 1.575,8.175 0.75,7.35 0.75,3.875 3.254,1.371 Y3.2 4.55,1.326 C24.2
NetC25_2: C25.2 U7.3 Y3.1 | length 13.8
  Bottom Layer w0.3: U7.3@4.175,7.675 2.375,7.675 1.725,7.025 1.725,4.625 3.25,3.1 5.1,3.1 6.829,1.371 Y3.1 7,1.326 C25.2
NetC27_2: C27.2 R22.1 U7.7 | length 7.5
  Top Layer w0.3: R22.1 2.45,8.6 2.45,9.625 ; C27.2 2.45,9.625 ; v1(6.075,9.675) 2.5,9.675 2.45,9.625
  Bottom Layer w0.3: U7.7@4.175,9.675 v1(6.075,9.675)
NetC34_2: C34.2 U9.6 | length 3.2
  Bottom Layer w0.3: C34.2 5.45,63.2 6.635,62.015 U9.6
NetCT_2: CT.2 D6.2 R8.2 | length 4.3
  Top Layer w0.5: D6.2@31.475,46.95 33.801,46.95 CT.2
  Bottom Layer w0.5: R8.2 33.851,48.949 CT.2
NetD1_1: D1.1 T1.6 | length 4
  Top Layer w1: D1.1 27.64,29.925 T1.6
NetD2_1: D2.1 K1.2 Q3.3 | length 7.5
  Bottom Layer w0.5: Q3.3 12.175,25.3 D2.1 13.725,25.225 K1.2
NetD3_2: D3.2 R18.2 R21.1 | length 4.2
  Bottom Layer w0.5: R18.2 R21.1 D3.2
NetD4_1: D4.1 R25.1 | length 2.3
  Bottom Layer w0.3: D4.1 21.125,16.115 R25.1
NetD4_3: D4.3 R24.1 | length 2.3
  Bottom Layer w0.3: R24.1 16.025,16.115 D4.3
NetD5_1: D5.1 T1.2 | length 4.3
  Top Layer w0.5: T1.2 36.425,41.1 38.425,43.1 D5.1
NetD6_1: D6.1 T1.3 U1.8 | length 18.7
  Top Layer w0.5: D6.1@31.475,43.45 31.505,43.42 T1.3
  Bottom Layer w0.5: U1.8@26.525,53.626 26.525,48.625 31.505,43.645 T1.3
NetK1_5: K1.5 P3.2 | length 14.3
  Top Layer w2: K1.5 16.2,36.85 21.122,41.772 P3.2
NetP3_3: P3.3 U9.3 U9.4 | length 7.7
  Bottom Layer w2: P3.3 13.122,61.353
NetP5_1: P5.1 U7.21 | length 3.1
  Bottom Layer w0.3: P5.1 9.475,15.275 U7.21@9.475,13.475
NetP5_2: P5.2 U7.22 | length 3.2
  Bottom Layer w0.3: U7.22@9.975,13.475 9.975,15.085 P5.2
NetQ1_1: Q1.1 R10.2 R11.2 | length 3.6
  Bottom Layer w0.3: R11.2 31.55,23.55 Q1.1 31.65,21.7 R10.2
NetQ1_3: Q1.3 R9.1 U4.1 | length 6
  Bottom Layer w0.3: R9.1 34.15,26.45 34.15,23.25 34.7,22.7 U4.1
NetQ3_1: Q3.1 R16.2 R17.1 | length 3.7
  Bottom Layer w0.5: Q3.1 18.15,28.775 R16.2
NetQ4_1: Q4.1 R21.2 | length 2.4
  Bottom Layer w0.5: R21.2 29.675,15.775 Q4.1
NetR4_1: R4.1 U2.1 | length 23.1
  Top Layer w0.5: v1(1.15,63.475) 1.15,66.9 12.5,78.25 U2.1 U2.1@16.125,78.25
NetR12_2: R12.2 R13.1 U4.3 U5.8 | length 11.8
  Bottom Layer w0.5: R12.2 36.675,18.375 R13.1 36.9,20.075 38.7,21.875 U4.3@38.7,23.75
  Bottom Layer w0.8: U4.3@38.7,23.75 38.8,23.85 U5.8
NetR13_2: R13.2 U5.3 | length 2
  Bottom Layer w0.3: U5.3 R13.2
NetR14_1: R14.1 U5.12 | length 2.3
  Bottom Layer w0.5: U5.12 27.05,20.625 R14.1
NetR15_1: R15.1 U5.10 | length 2.3
  Bottom Layer w0.3: U5.10 27.05,24.625 R15.1
NetR20_1: R20.1 U7.44 | length 3.2
  Top Layer w0.3: v1(7.475,7.25) 7.5,7.225 R20.1
  Bottom Layer w0.3: U7.44@7.475,5.375 v1(7.475,7.25)
NetR26_1: R26.1 S1.5 | length 3
  Top Layer w0.3: R26.1 18.4,4.05 S1.5
NetU6_1: U6.1 Y1.1 | length 3.3
  Bottom Layer w0.3: U6.1 29.479,0.679 Y1.1@30.5,1.7
NetU6_16: U6.16 Y1.2 | length 2.9
  Bottom Layer w0.3: U6.16 30.495,6.775 Y1.2@30.5,6.78
RELAY_ONOFF: R16.1 U7.25 | length 28.4
  Top Layer w0.3: v1(14.375,14.175) 21.775,14.175 21.788,14.162 22.875,15.25 v1(22.875,25.925)
  Bottom Layer w0.3: U7.25@12.275,12.175 13.725,12.175 14.375,12.825 v1(14.375,14.175) ; R16.1 21.725,28.8 22.875,27.65 v1(22.875,25.925)
SWCLK: P6.3 U7.37 | length 6.8
  Bottom Layer w0.3: U7.37@10.975,5.375 10.975,3.825 11.425,3.375 11.425,0.65 12.55,-0.475 P6.3
SWDIO: P6.1 U7.34 | length 15.7
  Bottom Layer w0.3: U7.34@12.275,7.675 13.825,7.675 14.4,7.1 14.4,-4.005 P6.1
XGND: BD1.4 C1.2 C2.2 C3.2 C6.2 C7.2 C9.1 R1.2 T1.1 U1.5 U2.3 | length 85
  Top Layer w0.5: U2.3 22.94,75.71 24.225,74.425 v1(24.225,64.95) ; T1.1 40.665,41.95 BD1.4@40.665,56.75
  Bottom Layer w0.5: C9.1 7.202,75.65 C2.2 18.925,75.775 v1(22.275,75.775) 22.975,75.075 C3.2 ; C6.2 C7.2@26.5,64.85 ; C7.2 C7.2@26.5,64.85 ; U1.5@30.18,53.781 35.3,53.781 ; 40.91,50.675 40.91,51.9 39.029,53.781 35.3,53.781 ; C7.2@26.5,64.85 27.6,64.85 27.625,64.875 32.625,64.875 35.3,62.2 35.3,53.781
pads on no net: K1.4 P3.1 U5.2 U5.11 U6.6 U6.14 U7.2 U7.10 U7.11 U7.14 U7.15 U7.16 U7.17 U7.26 U7.38 U7.39 U7.40 U7.41 U7.43 U7.45 U7.46 Y3.

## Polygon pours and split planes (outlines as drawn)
GND on Top Layer "Top Layer-No Net" (solid, remove dead copper, shelved, pour order 0): -3.984,40.425 17.25,40.425 41,40.425 41,-4.9 41,-7.75 32.2,-7.75 -3.625,-7.75 -3.625,-7.775 -3.625,-7.7 -4.05,-7.7
GND on Bottom Layer "Top Layer-No Net" (solid, remove dead copper, shelved, pour order 2): -4.008,40.425 17.4,40.425 41.025,40.425 41.025,-5.15 41.025,-7.75 31.475,-7.75 -3.975,-7.75 -3.975,-6.725

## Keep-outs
Keep-Out Layer:
  lines w0.1: -4,0.05 ccw(c3.898,0.152) 4,-7.747 ; -4,-0.172 -4,40.475 -5.5,40.475 -5.5,67.65 cw(c18.461,50.394) 42.496,67.546 ; -3.997,-0.054 -3.996,-0.102 ; -3.995,-0.173 -3.995,-0.172 ; 3.898,-7.75 33.2,-7.75 ccw(c33.098,0.148) 40.997,0.25 ; 24.25,47.075 26.25,47.075 26.25,39.45 24.275,39.45 24.275,46.95 ; 41,0.025 41,40.475 42.475,40.475 42.5,40.475 42.5,67.546 ; 9.425,42.15 11.375,42.15 11.375,50.225 9.425,50.225 9.425,42.15 ; 17.75,54.875 17.75,59.825 19.95,59.825 19.95,54.875 17.75,54.875 ; 28.625,33.7 39.525,33.7 39.525,37.65 28.625,37.65 28.625,33.7

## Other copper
Top Layer:
  pour cut-out: 27.025,-4.1 31.025,-4.1 31.025,-7.75 27.025,-7.75
  pour cut-out: 5.575,36.9 5.575,14.95 22.45,14.95 22.45,25.262 46.1,25.262 46.1,76.375 -1.875,76.375 -1.875,36.9
Bottom Layer:
  pour cut-out: 25.725,-0.2 25.725,-7.75 31.025,-7.75 31.025,-4.075 27,-4.075 27,-0.2
  pour cut-out: 2.225,40.4 2.225,18.45 19.1,18.45 19.1,28.55 42.75,28.55 42.75,79.875 -5.225,79.875 -5.225,40.4

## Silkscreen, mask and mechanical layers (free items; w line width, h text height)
Top Overlay:
  circle w0.1: c0,0 r4
  circle w0.1: c37,0 r4
  circle w0.1: c-3,66.7 r2
  circle w0.1: c40,66.7 r2
  region: 15.175,36.6 15.175,37.3 20.007,42.132 20.007,44.457 22.075,46.525 22.125,46.475 22.125,41.325 17.4,36.6
  region: 13.912,42.562 12.5,41.15 9.4,38.05 9.4,22.4 11.525,22.4 11.525,37.1 12.988,38.562 14.475,40.05 15.45,41.025
  lines w0.4: -4,40.475 1.75,40.475 1.75,18.775 18.575,18.775 18.575,28.45 40.75,28.45
  text "3V3" at 0.575,20.925 h1.52 r90
  text "R2" at 2.225,13.575 h1.52
  text "T2" at 5.025,13.525 h1.52
  text "T3" at 7.925,13.5 h1.52
  text "R3" at 10.575,13.475 h1.52
  text "G" at 13.1,13.475 h1.52
  text "T1" at 16.8,9.225 h1.52
  text "R1" at 16.925,7.65 h1.52
  text "CLK" at 15.025,-1.525 h1.52
  text "GND" at 31.125,-3.7 h1.52
  text "ASKTX" at 6.875,-4.825 h1.52 r90
  text "DIO" at 9,-7 h1.52
Bottom Overlay:
  rectangle: 12.125,65.325 14.2,70.9
  rectangle: 12.125,54.875 14.15,60.025
  lines w0.4: -4,40.475 1.725,40.475 1.725,18.825 18.6,18.825 18.6,28.475 40.75,28.475
  text "220V零线" at 11.025,72.85 h1.6 r90
  text "220V火线" at 17.85,47.825 h1.6
Mechanical 15:
  lines w0.1: -3.925,0 40.95,0 ; -3.25,66.7 40.25,66.7 ; 18.5,-7.8 18.5,80.2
